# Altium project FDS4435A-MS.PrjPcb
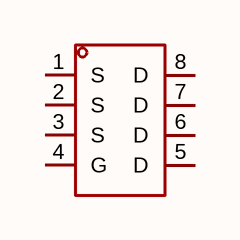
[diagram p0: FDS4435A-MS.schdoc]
1 sheet, 1 parts. Net scope: global (net labels, ports and power ports of the same name join across sheets).

## Sheet FDS4435A-MS.schdoc
size 127 x 101 mm

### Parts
Q?  fds4435a-ms  [SOP-8_L4.9-W3.9-P1.27-LS6.0-BL]  (value not drawn)

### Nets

Not connected (* = marked no-connect by the designer): Q? 1(S) 2(S) 3(S) 4(G) 5(D) 6(D) 7(D) 8(D)

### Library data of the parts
Q? = fds4435a-ms: 类型:-;漏源电压(Vdss):30V;连续漏极电流(Id):9A;导通电阻(RDS(on)@Vgs,Id):16mΩ@10V;功率:2.1W;阈值电压(Vgs(th)@Id):1.6V@250uA;; Manufacturer: MSKSEMI(美森科); AddInBom: yes; ModelId: 75c24a7891ee4dd6bdac16a7163ff87e; ModelName: SOP-8_L4.9-W3.9-P1.27-LS6.0-BL-1; ModelTransform: 192.913,236.22,0,0,0,0,-0.393,2.749,0; Drain Source Voltage (Vdss): 30V; Continuous Drain Current (Id): 9A; Power Dissipation (Pd): 2.1W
